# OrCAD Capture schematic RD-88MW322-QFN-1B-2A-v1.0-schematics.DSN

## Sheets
1 BLOCK DIAGRAM, TOC: title: RD-88MW322-QFN-1B-2A V1.0 Schematic; rev: 1
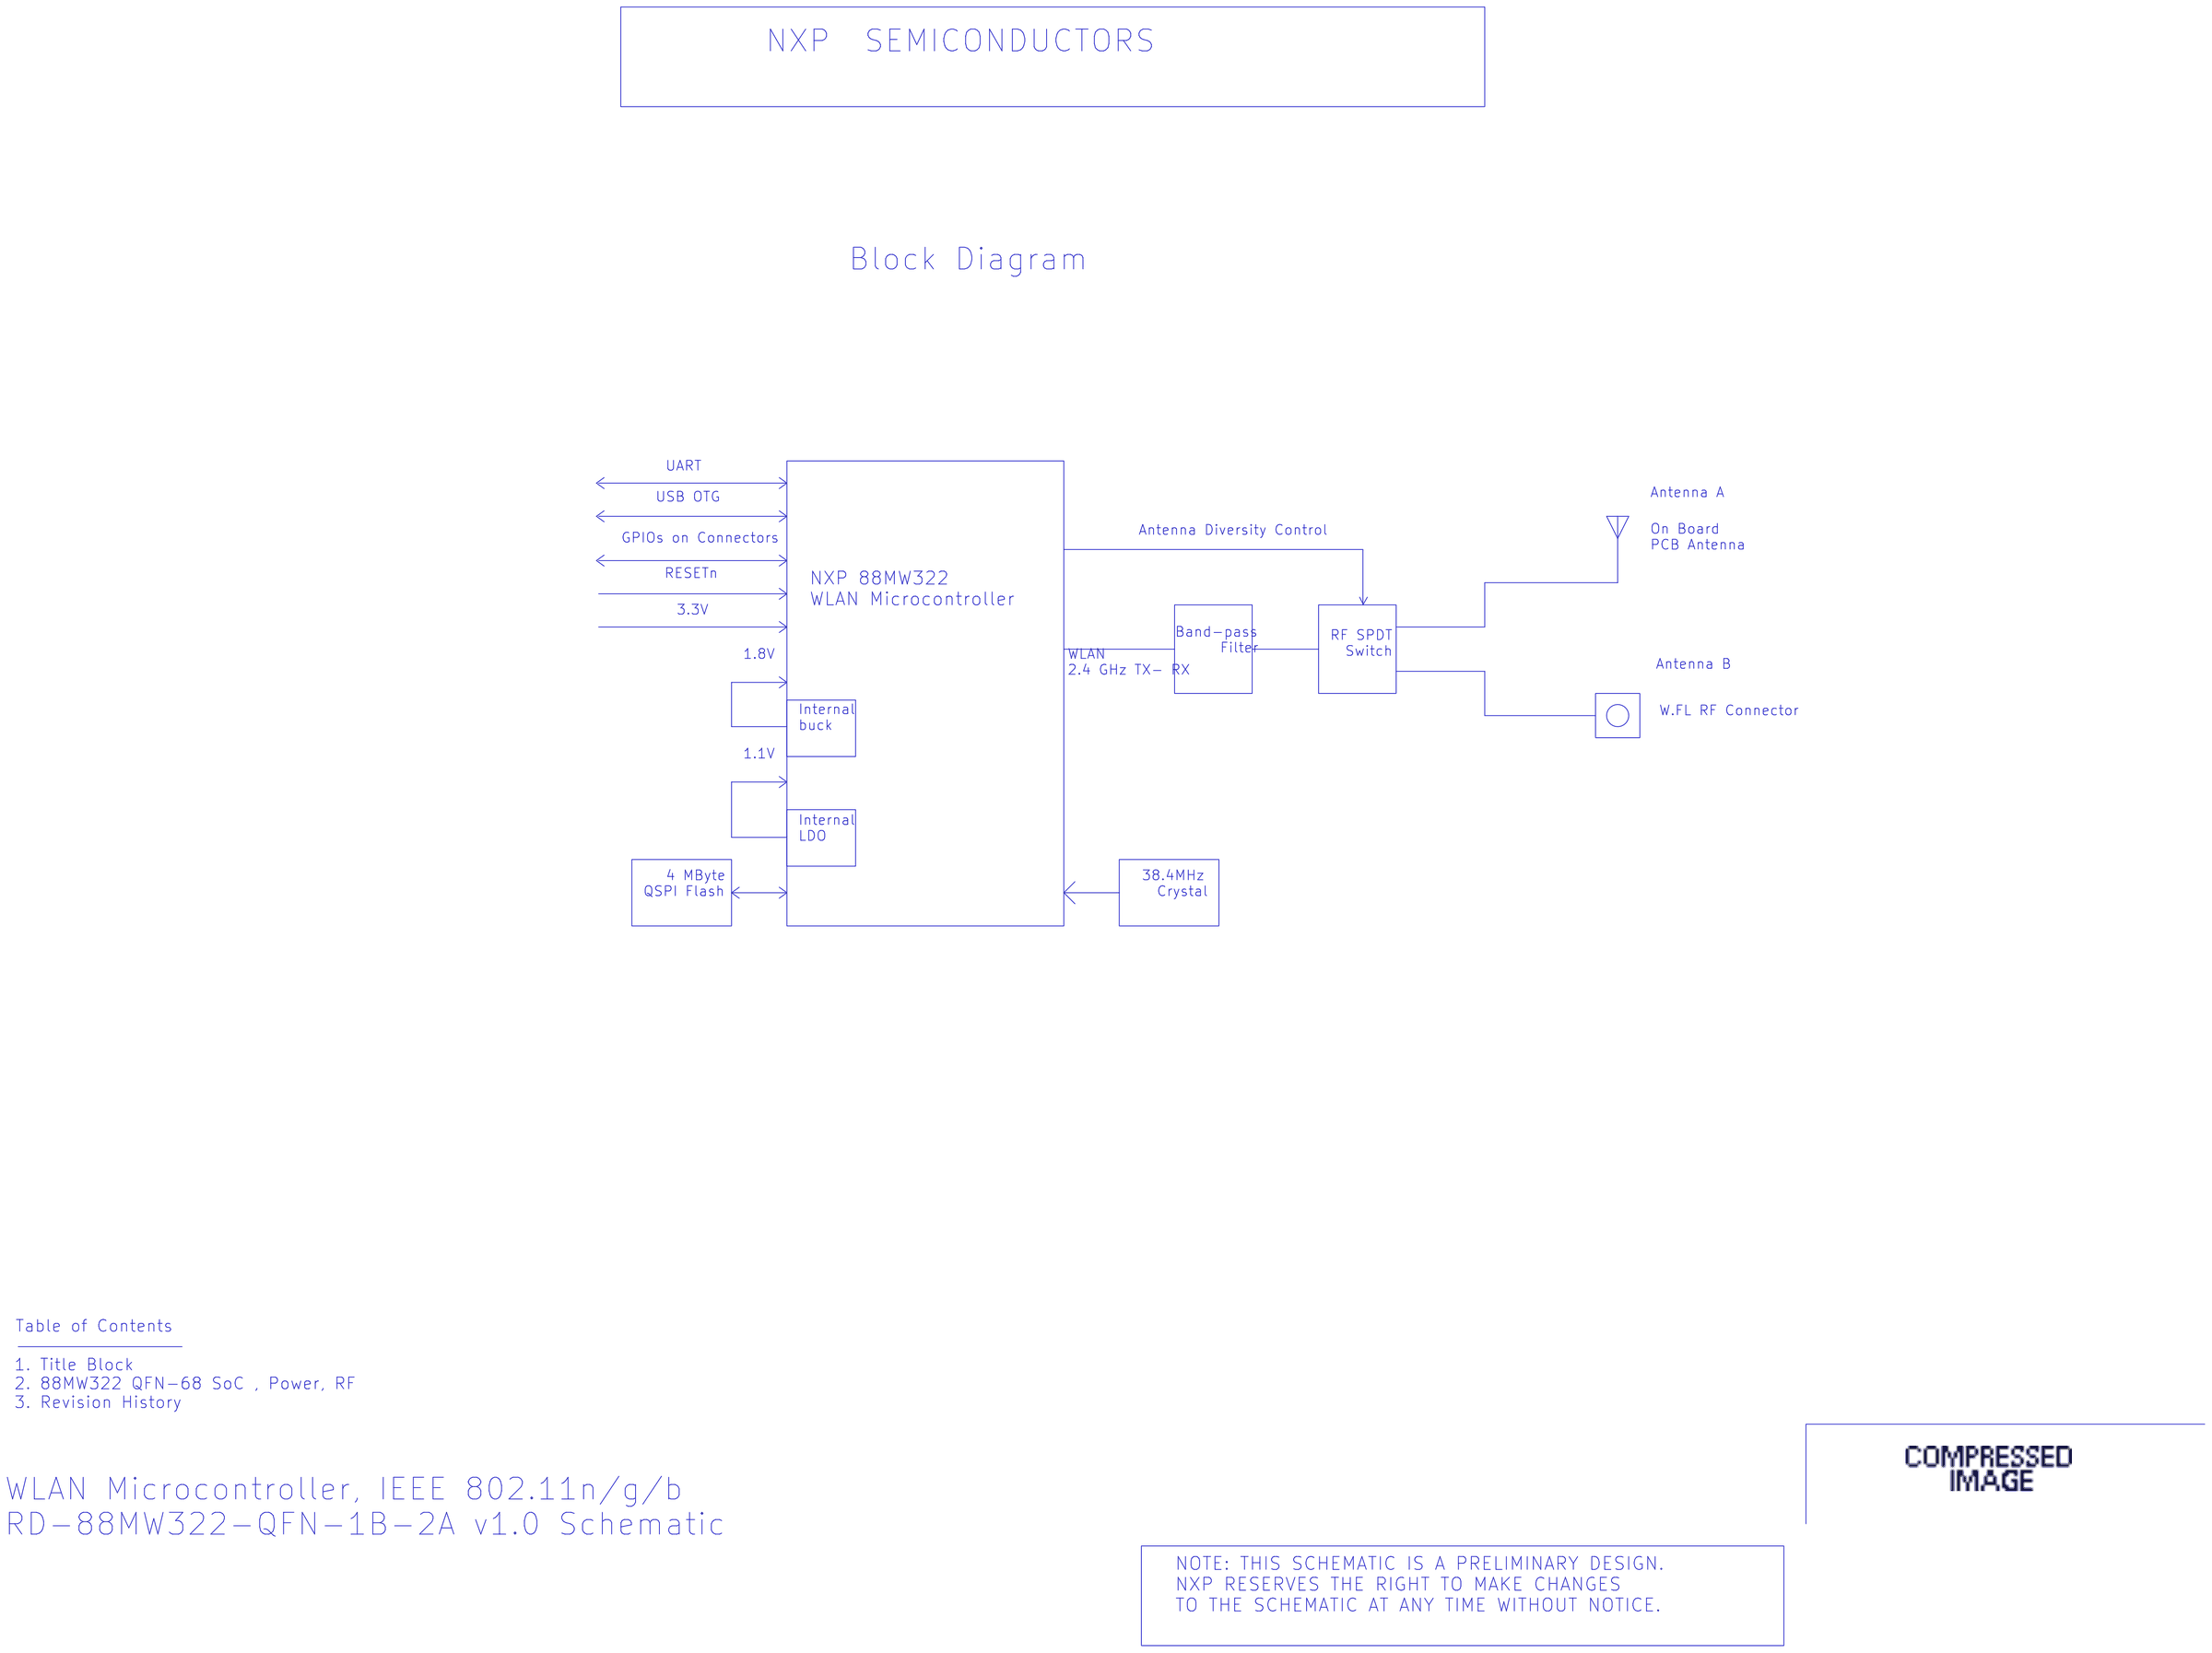
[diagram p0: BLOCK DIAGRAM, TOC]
2 88MW322 QFN-88 SoC_Power_RF: size C
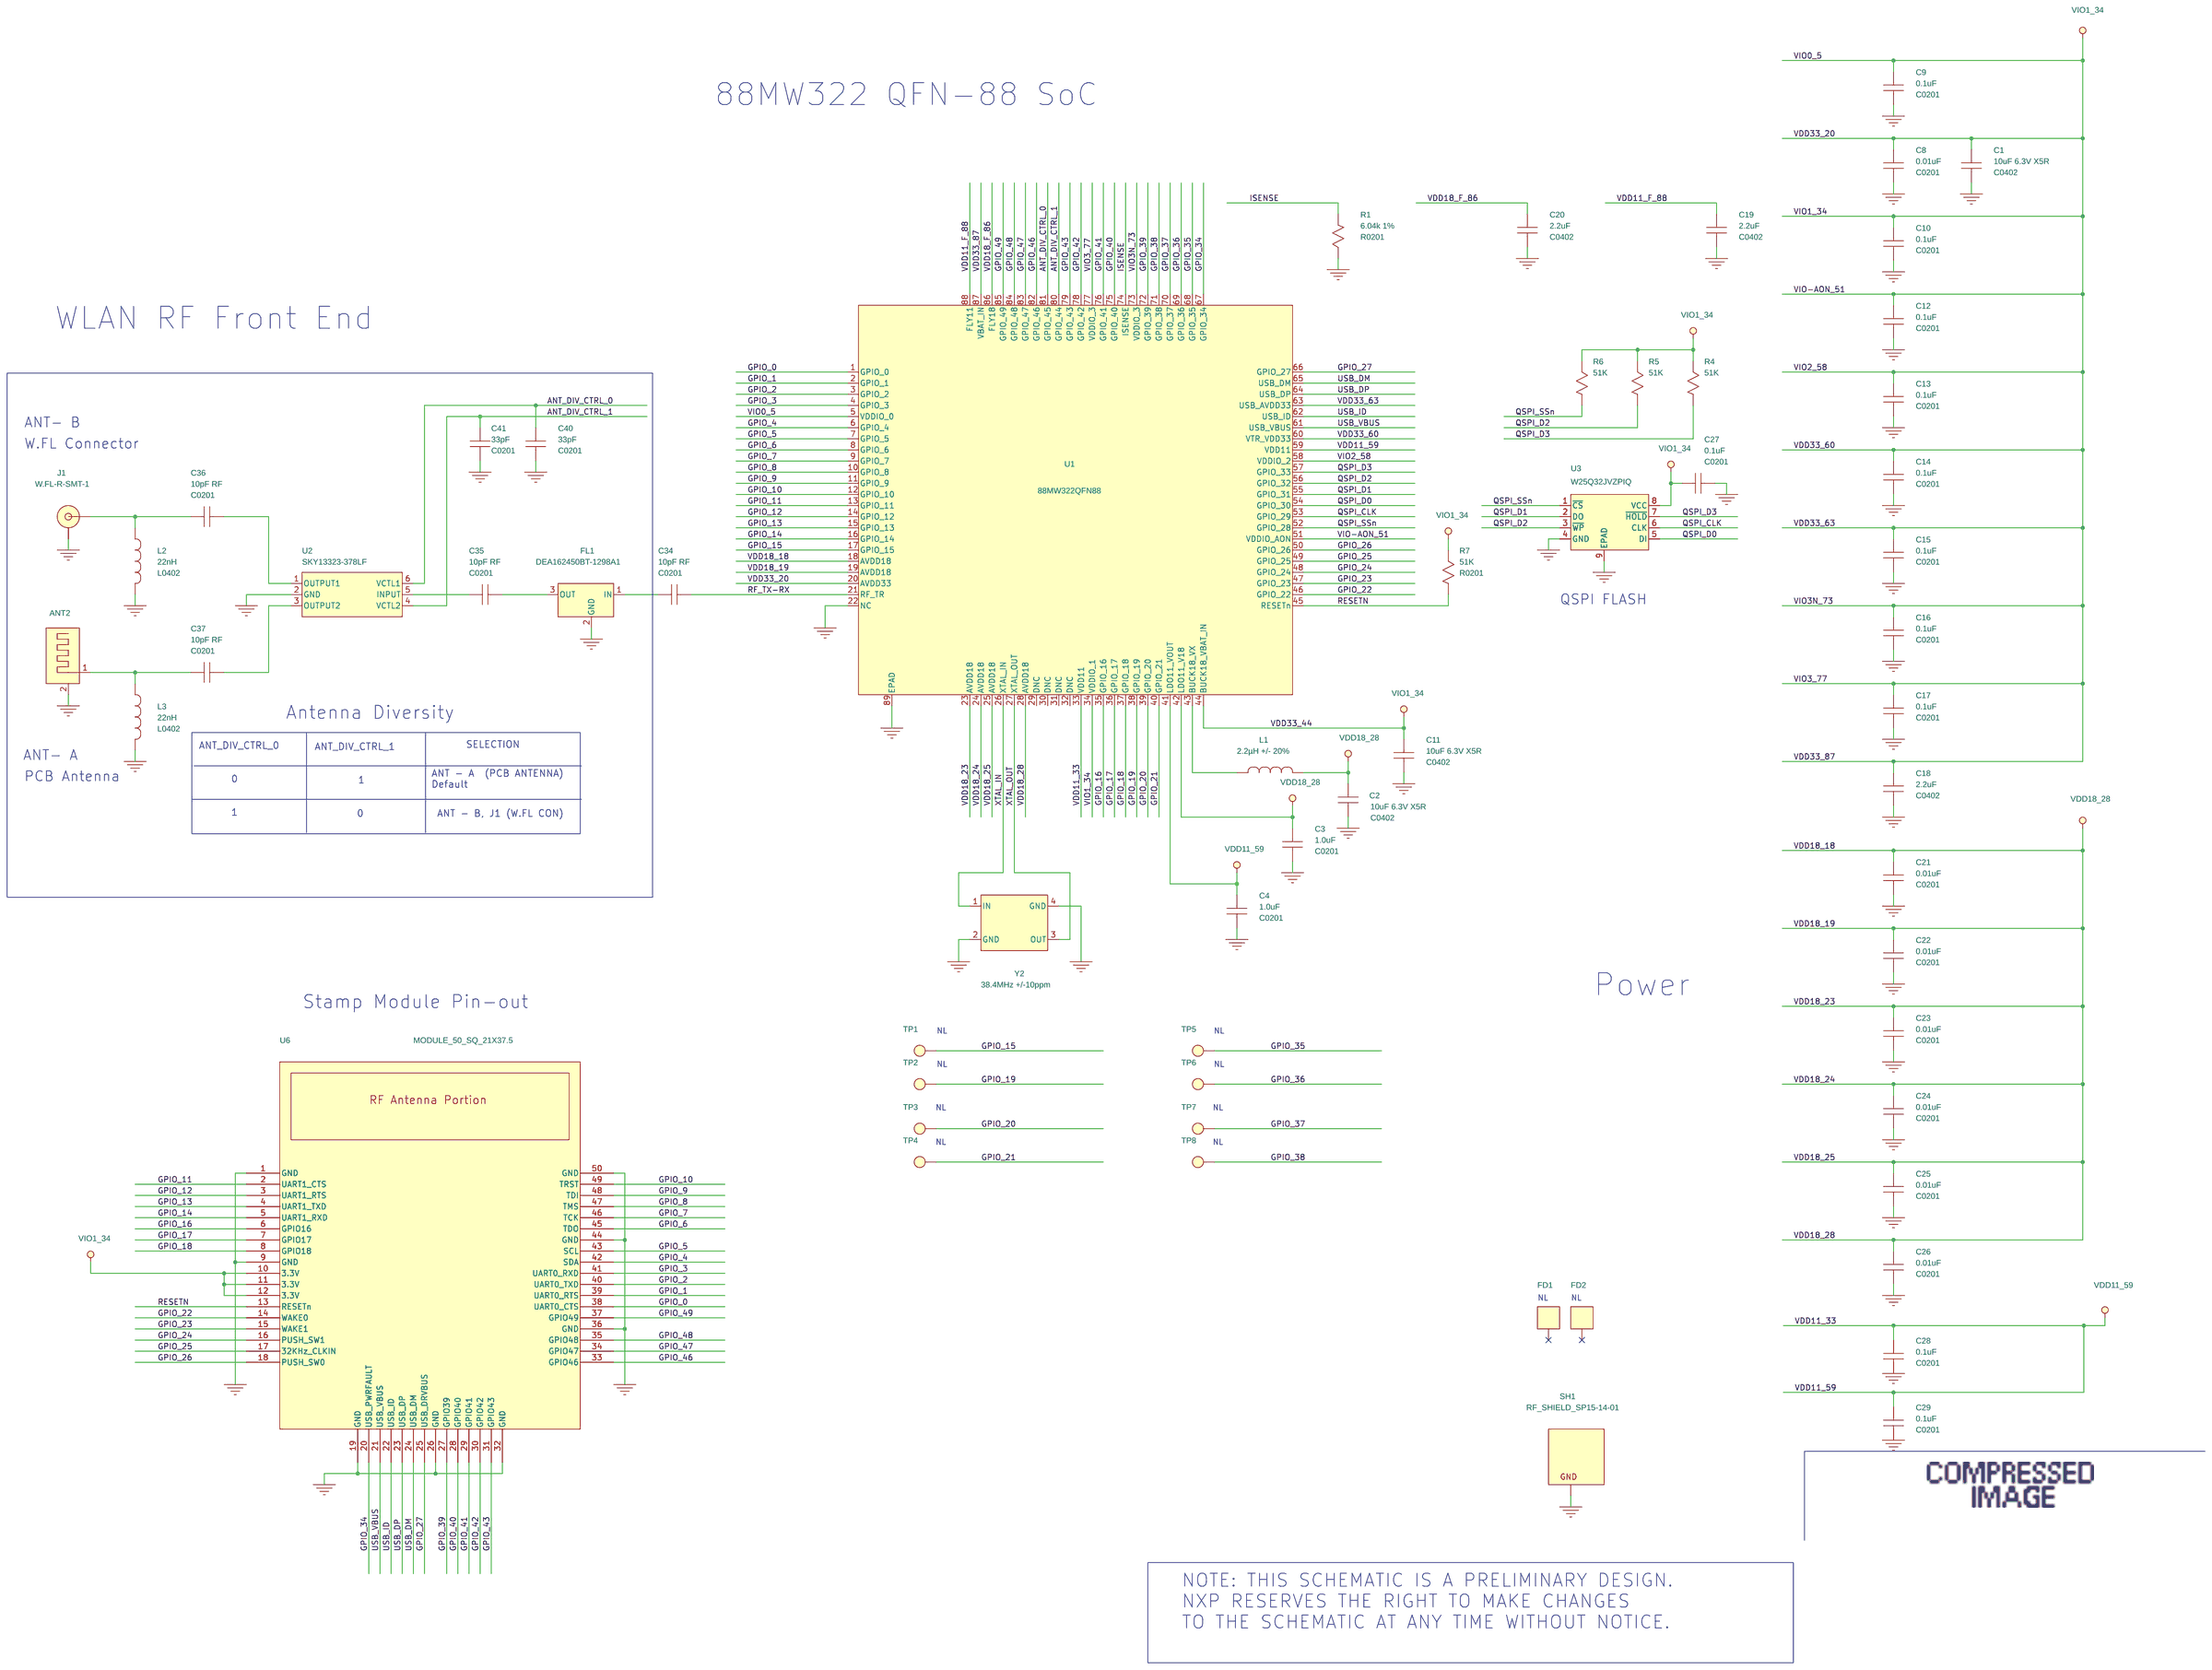
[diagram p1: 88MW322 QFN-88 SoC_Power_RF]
3 REVISION HISTORY
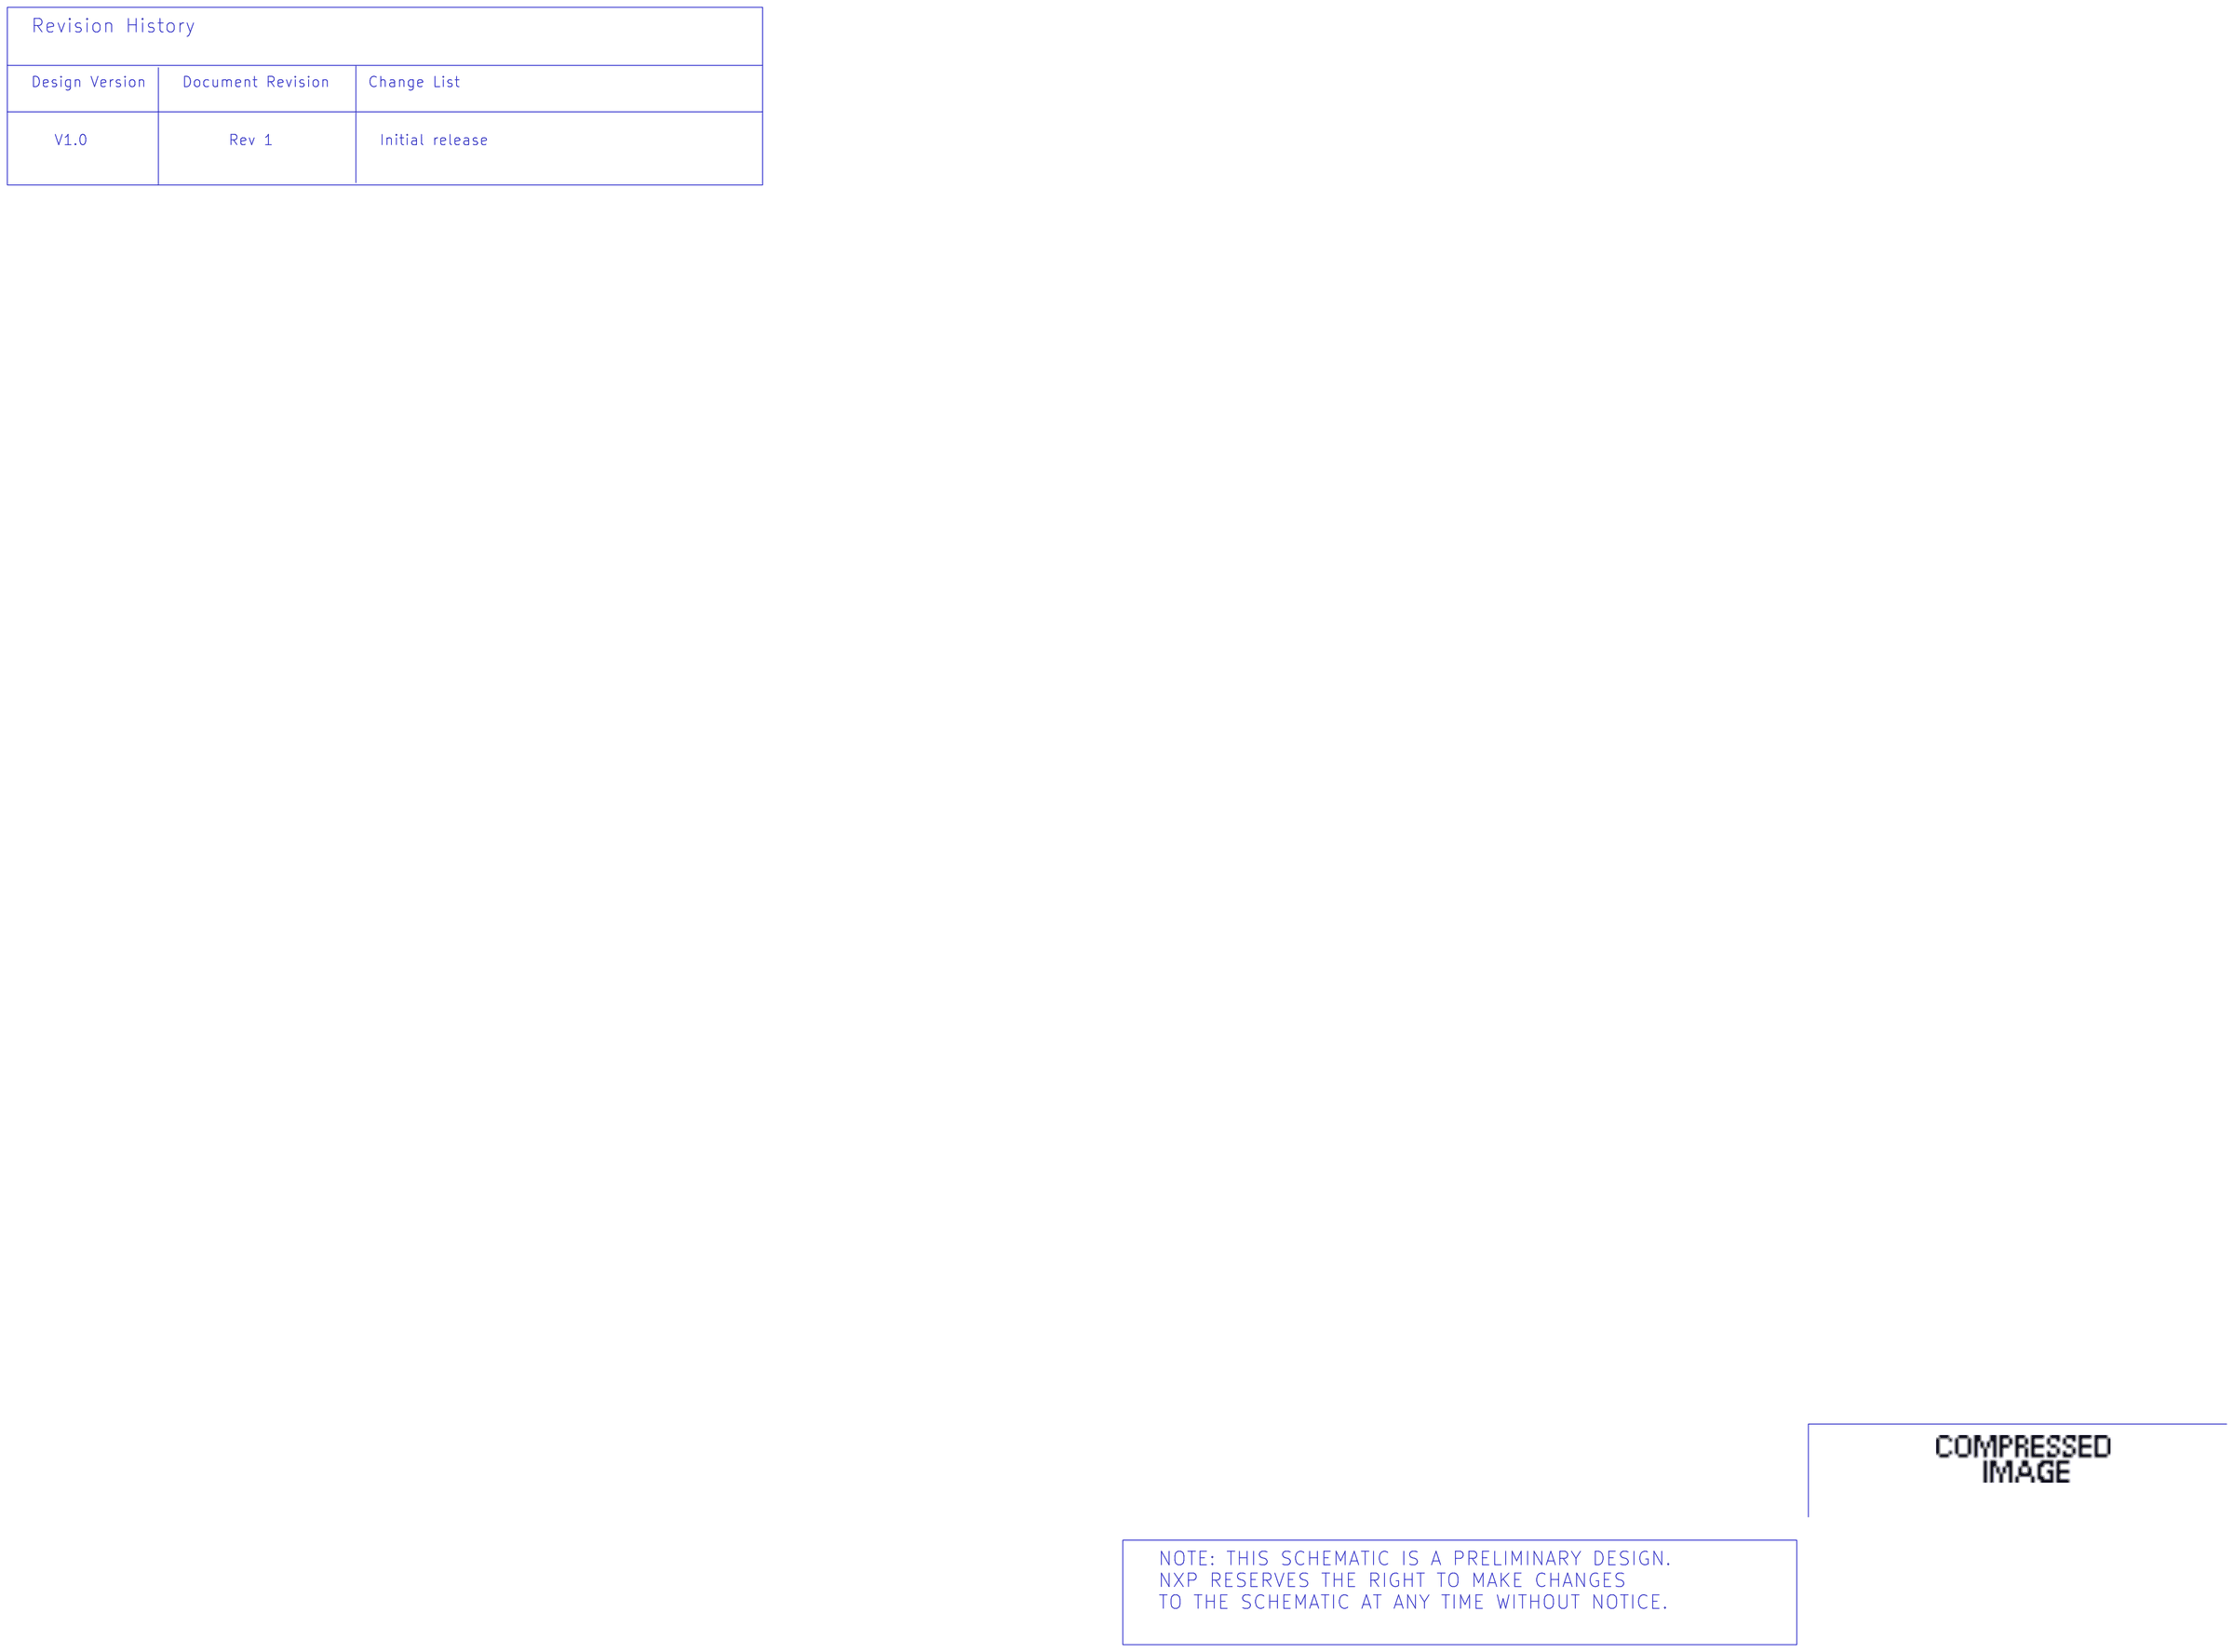
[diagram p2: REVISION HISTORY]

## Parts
ANT2  PCB Micro-strip Patch Antenna  [SDIO_ANT_SINGLE_INVERT_SOUTH]
C1  10uF 6.3V X5R  [C0402]
C2  10uF 6.3V X5R  [C0402]
C3  1.0uF  [C0201]
C4  1.0uF  [C0201]
C8  0.01uF  [C0201]
C9  0.1uF  [C0201]
C10  0.1uF  [C0201]
C11  10uF 6.3V X5R  [C0402]
C12  0.1uF  [C0201]
C13  0.1uF  [C0201]
C14  0.1uF  [C0201]
C15  0.1uF  [C0201]
C16  0.1uF  [C0201]
C17  0.1uF  [C0201]
C18  2.2uF  [C0402]
C19  2.2uF  [C0402]
C20  2.2uF  [C0402]
C21  0.01uF  [C0201]
C22  0.01uF  [C0201]
C23  0.01uF  [C0201]
C24  0.01uF  [C0201]
C25  0.01uF  [C0201]
C26  0.01uF  [C0201]
C27  0.1uF  [C0201]
C28  0.1uF  [C0201]
C29  0.1uF  [C0201]
C34  10pF RF  [C0201]
C35  10pF RF  [C0201]
C36  10pF RF  [C0201]
C37  10pF RF  [C0201]
C40  33pF  [C0201]
C41  33pF  [C0201]
FD1  NL  [FIDUCIAL_25MP-40MM]
FD2  NL  [FIDUCIAL_25MP-40MM]
FL1  DEA162450BT-1298A1  [RF_TDK_BPF_LGA3_1.6X0.8]
J1  W.FL-R-SMT-1  [CON_WFL_MALE_2X2MM_SMD4]
L1  2.2µH +/- 20%  [L0805]
L2  22nH  [L0402]
L3  22nH  [L0402]
R1  6.04k 1%  [R0201]
R4  51K  [R0201]
R5  51K  [R0201]
R6  51K  [R0201]
R7  51K  [R0201]
SH1  RF_SHIELD_SP15-14-01  [RF_SHIELD_SP15-14-01]
TP1  NL  [TP_SMPAD30MIL]
TP2  NL  [TP_SMPAD30MIL]
TP3  NL  [TP_SMPAD30MIL]
TP4  NL  [TP_SMPAD30MIL]
TP5  NL  [TP_SMPAD30MIL]
TP6  NL  [TP_SMPAD30MIL]
TP7  NL  [TP_SMPAD30MIL]
TP8  NL  [TP_SMPAD30MIL]
U1  88MW322QFN88  [MRVL_QFN88LP40_10X10_NXU]
U2  SKY13323-378LF  [RF_SKY_SPDT_MLPD6P35_1X1X0.5]
U3  W25Q32JVZPIQ  [IC_WBOND_WSON8_ZP]
U6  MODULE  [MODULE_50_SQ_21X37.5]
Y2  38.4MHz +/-10ppm  [XTAL_TXC_SMD_1.6X1.2MM]

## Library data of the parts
ANT2 = ON-Board_ANT_0
C1 C2 C11 = CAP_NP: CAP CER 10uF 20% 6.3V X5R 0402 (0.5MM); ManufacturerPn1: Murata GRM155R60J106ME44D; ManufacturerPn2: TDK C1005X5R0J106M050BC; Mfg1MrvlAvl: 0; Mfg2MrvlAvl: 0; Mfg3MrvlAvl: 0; ObsoletedByPartID: 0; Part Number: 5044-001-002287; Part Type: CAP; SourceLibrary: PARTS.OLB
C3 C4 = CAP_NP: CAP CER 1uF 20% 6.3V X5R 0201 (0.3MM); ManufacturerPn1: TDK C0603X5R0J105M030BC; Mfg1MrvlAvl: 0; Mfg2MrvlAvl: 0; Mfg3MrvlAvl: 0; ObsoletedByPartID: 0; Part Number: 5044-001-002324; Part Type: CAP; SourceLibrary: PARTS.OLB
C8 C21-C26 = CAP_NP: CAP CER 0.01uF 10% 10V X7R 0201 (0.3MM); ManufacturerPn1: MURATA GRM033R71A103K; ManufacturerPn2: WALSIN 0201B103K100CT; ManufacturerPn3: TDK C0603X7R1A103K; Mfg1MrvlAvl: 0; Mfg2MrvlAvl: 0; Mfg3MrvlAvl: 0; ObsoletedByPartID: 0; Part Number: 5044-001-001487; Part Type: CAP; SourceLibrary: PARTS.OLB
C9 C10 C12-C17 C27-C29 = CAP_NP: CAP CER 0.1uF 10% 6.3V X5R 0201 (0.3MM); ManufacturerPn1: MURATA GRM033R60J104K; ManufacturerPn2: WALSIN 0201X104K6R3CT; ManufacturerPn3: TDK C0603X5R0J104K; Mfg1MrvlAvl: 0; Mfg2MrvlAvl: 0; Mfg3MrvlAvl: 0; ObsoletedByPartID: 0; Part Number: 5044-001-001493; Part Type: CAP; SourceLibrary: PARTS.OLB
C18-C20 = CAP_NP: CAP CER 2.2UF 10% 6.3V  X5R 0402 (0.3MM); ManufacturerPn1: TDK C1005X5R0J225K050BC; Mfg1MrvlAvl: 0; Mfg2MrvlAvl: 0; Mfg3MrvlAvl: 0; ObsoletedByPartID: 0; Part Number: 5044-001-002325; Part Type: CAP; SourceLibrary: PARTS.OLB
C34-C37 = CAP_NP: CAP CER 10pF 5% 25V C0H 0201 (0.3MM); ManufacturerPn1: Murata GJM0336C1E100JB01; Mfg1MrvlAvl: 0; Mfg2MrvlAvl: 0; Mfg3MrvlAvl: 0; ObsoletedByPartID: 0; Part Number: 5044-001-002305; Part Type: CAP; SourceLibrary: PARTS.OLB
C40 C41 = CAP_NP: CAP CER 33pF 5% 25V C0G 0201 (0.3MM); ManufacturerPn1: MURATA GRM0335C1E330J; ManufacturerPn2: WALSIN 0201N330J250LT; ManufacturerPn3: TDK C0603C0G1E330J; Mfg1MrvlAvl: 0; Mfg2MrvlAvl: 0; Mfg3MrvlAvl: 0; Notes: 50V ok if 25V not available; ObsoletedByPartID: 0; Part Number: 5044-001-001469; Part Type: CAP; SourceLibrary: PARTS.OLB
FD1 FD2 = FIDUCIAL: FIDUCIAL ULTRA SMALL 25 MIL PAD / 40 MIL SOLDER MASK OPENING; ManufacturerPn1: FIDUCIAL_25MPAD-40MMASK; ManufacturerPn2: NA; ManufacturerPn3: NA; Mfg1MrvlAvl: 0; Mfg2MrvlAvl: 0; Mfg3MrvlAvl: 0; ObsoletedByPartID: 0; Part Number: FIDUCIAL_25MPAD-40MMASK; Part Type: MECH; SourceLibrary: PARTS.OLB
FL1 = RF_DEA162450BT-1298A1: FILTER BP 2450MHz +/-50MHz IL=1.3dB MAX LGA-3 1.6x0.8x0.6mm; ManufacturerPn1: TDK DEA162450BT-1298A1; Mfg1MrvlAvl: 0; Mfg2MrvlAvl: 0; Mfg3MrvlAvl: 0; ObsoletedByPartID: 0; Part Number: 5044-001-002438; Part Type: FILTER; SourceLibrary: PARTS.OLB
J1 = CON_W.FL-R-SMT-1: CONN RF W.FL COAX MALE 2.0x2.0x0.85MM  SMD; ManufacturerPn1: HIROSE W.FL-R-SMT-1(10); ManufacturerPn2: IPEX 20369-001E; Mfg1MrvlAvl: 0; Mfg2MrvlAvl: 0; Mfg3MrvlAvl: 0; ObsoletedByPartID: 0; Part Number: 5044-001-002271; Part Type: CONN; SourceLibrary: PARTS.OLB
L1 = INDUCTOR: IND WWC 2.2UH +/-20% 1000mA 0805 SMD; ManufacturerPn1: TAIYO YUDEN BRC2012T2R2MD; Mfg1MrvlAvl: 0; Mfg2MrvlAvl: 0; Mfg3MrvlAvl: 0; ObsoletedByPartID: 0; Part Number: 5044-001-002447; Part Type: IND; SourceLibrary: PARTS.OLB
L2 L3 = INDUCTOR: IND MLC 22nH +/-5% 300mA 0402 SMD Hi-Q; ManufacturerPn1: MURATA LQG15HS22NJ02; ManufacturerPn2: TDK MLG1005S22NJ; Mfg1MrvlAvl: 0; Mfg2MrvlAvl: 0; Mfg3MrvlAvl: 0; ObsoletedByPartID: 0; Part Number: 5044-001-001658; Part Type: IND; SourceLibrary: PARTS.OLB
R1 = RES: RES THICK FILM 6.04K OHM 1/20W 1% 0201 SMD; ManufacturerPn1: Cyntec PFR03S-6041-FNH; ManufacturerPn2: Walsin WR02X6041FAL; ManufacturerPn3: Yageo RC0201FR-076K04L; Mfg1MrvlAvl: 0; Mfg2MrvlAvl: 0; Mfg3MrvlAvl: 0; ObsoletedByPartID: 0; Part Number: 5044-001-000263; ProtoPriceTargetPerUnit: 0.00800; SourceLibrary: PARTS.OLB
R4-R7 = RES: RES THICK FILM 51K OHM 1/20W 5% 0201 SMD; ManufacturerPn1: Cyntec PFR03S-513-JNH; ManufacturerPn2: Walsin WR02X513 JAL; ManufacturerPn3: Yageo RC0201JR-0751KL; Mfg1MrvlAvl: 0; Mfg2MrvlAvl: 0; Mfg3MrvlAvl: 0; ObsoletedByPartID: 0; Part Number: 5044-001-000577; ProtoPriceTargetPerUnit: 0.00500; SourceLibrary: PARTS.OLB
SH1 = RF_SHIELD_TH2: RF SHIELD RD-MC200W8801-V2 1-PC SPTE 0.15MM +/-0.01MM THICK 28x18.4x2mm; ManufacturerPn1: BRIGHT-LINK SP15-14-01; ManufacturerPn2: AKS ASH0194; Mfg1MrvlAvl: 0; Mfg2MrvlAvl: 0; Mfg3MrvlAvl: 0; ObsoletedByPartID: 0; Part Number: 5044-001-002392; Part Type: MECH; SourceLibrary: PARTS.OLB
TP1-TP8 = TESTPOINT: MRVL SMD TESTPOINT SIZE 30 MIL; ManufacturerPn1: MRVL TP30MIL; Mfg1MrvlAvl: 0; Mfg2MrvlAvl: 0; Mfg3MrvlAvl: 0; ObsoletedByPartID: 0; Part Number: TP30MIL; Part Type: PCB; SourceLibrary: PARTS.OLB
U1 = 88MW322_QFN88L: IC MRVL 88MW322 WLAN MICROCONTROLLER SoC QFN88L 0.4mm 10x10x0.9mm; ManufacturerPn1: MRVL 88MW322-A0-NXU2E000; Mfg1MrvlAvl: 0; Mfg2MrvlAvl: 0; Mfg3MrvlAvl: 0; Notes: Pin compatible with 88MW302 (QFN88); ObsoletedByPartID: 0; Part Number: 88MW322A0NXU2E000; Part Type: Marvell; SourceLibrary: PARTS.OLB
U2 = RF_SKY_SPDT_SKY13323-378LF: IC RF SW SPDT 0.1GHz-3GHz VCTL 1.8V-5V MLPD-6 0.35mm 1x1x0.5mm; ManufacturerPn1: SKY SKY13323-378LF; Mfg1MrvlAvl: 0; Mfg2MrvlAvl: 0; Mfg3MrvlAvl: 0; ObsoletedByPartID: 0; OneHundredKPerMoPriceTarget: 0.00000; OneKkPerMoPriceTarget: 0.00000; Part Number: 5044-001-002253; Part Type: IC; ProtoPriceTargetPerUnit: 0.00000; SourceLibrary: PARTS.OLB
U3 = IC_WBOND_SQPI_FLASH_DQIO_WSON8: IC SPI+QPI SRL FLASH DUAL/QUAD I/O 32M 2.7-3.6V 133MHZ WSON-8 6x5x0.8mm; ManufacturerPn1: MACRONIX MX25L3233FZNI-08G; ManufacturerPn2: WINBOND W25Q32JVZPIQ; Mfg1MrvlAvl: 0; Mfg2MrvlAvl: 0; Mfg3MrvlAvl: 0; Notes: Drop-in replacement for W25Q32FVZPIG (EOL); ObsoletedByPartID: 0; Part Number: 5044-001-002937; Part Type: IC; SourceLibrary: PARTS.OLB
U6 = MODULE_4
Y2 = XTAL_TXC_SMD_1.6X1.2MM: XTAL 38.4MHz +/-10ppm FUND 10pF 60OHM -30C/+85C SMD 1.6X1.2X0.4mm; ManufacturerPn1: TXC 8Q38470003; Mfg1MrvlAvl: 0; Mfg2MrvlAvl: 0; Mfg3MrvlAvl: 0; ObsoletedByPartID: 0; Part Number: 5044-001-002327; Part Type: XTAL/OSC; SourceLibrary: PARTS.OLB

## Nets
+1.1V: C4.1 C28.1 C29.1 U1.33(VDD11) U1.41(LDO11_VOUT) U1.59(VDD11)
+1.8V: C2.1 C3.1 C21.1 C22.1 C23.1 C24.1 C25.1 C26.1 L1.2 U1.18(AVDD18) U1.19(AVDD18) U1.23(AVDD18) U1.24(AVDD18) U1.25(AVDD18) U1.28(AVDD18) U1.42(LDO11_V18)
+3.3V: C1.1 C8.1 C9.1 C10.1 C11.1 C12.1 C13.1 C14.1 C15.1 C16.1 C17.1 C18.1 C27.1 R4.1 R5.1 R6.1 R7.1 U1.5(VDDIO_0) U1.20(AVDD33) U1.34(VDDIO_1) U1.44(BUCK18_VBAT_IN) U1.51(VDDIO_AON) U1.58(VDDIO_2) U1.60(VTR_VDD33) U1.63(USB_AVDD33) U1.73(VDDIO_3) U1.77(VDDIO_3) U1.87(VBAT_IN) U3.8(VCC) U6.10(3.3V) U6.11(3.3V) U6.12(3.3V)
GND_POWER: ANT2.2 C1.2 C2.2 C3.2 C4.2 C8.2 C9.2 C10.2 C11.2 C12.2 C13.2 C14.2 C15.2 C16.2 C17.2 C18.2 C19.2 C20.2 C21.2 C22.2 C23.2 C24.2 C25.2 C26.2 C27.2 C28.2 C29.2 C40.2 C41.2 FL1.2(GND) J1.2(GND) J1.3(GND) J1.4(GND) L2.2 L3.2 R1.1 SH1.1(GND) SH1.2(GND) U1.22(NC) U1.89(EPAD) U2.2(GND) U3.4(GND) U3.9(EPAD) U6.1(GND) U6.9(GND) U6.19(GND) U6.26(GND) U6.32(GND) U6.36(GND) U6.44(GND) U6.50(GND) Y2.2(GND) Y2.4(GND)
VDD11_F_88: C19.1 U1.88(FLY11)
VDD18_F_86: C20.1 U1.86(FLY18)
ANT_DIV_CTRL_0: C40.1 U1.81(GPIO_45) U2.6(VCTL1)
ANT_DIV_CTRL_1: C41.1 U1.80(GPIO_44) U2.4(VCTL2)
GPIO_0: U1.1(GPIO_0) U6.38(UART0_CTS)
GPIO_1: U1.2(GPIO_1) U6.39(UART0_RTS)
GPIO_2: U1.3(GPIO_2) U6.40(UART0_TXD)
GPIO_3: U1.4(GPIO_3) U6.41(UART0_RXD)
GPIO_4: U1.6(GPIO_4) U6.42(SDA)
GPIO_5: U1.7(GPIO_5) U6.43(SCL)
GPIO_6: U1.8(GPIO_6) U6.45(TDO)
GPIO_7: U1.9(GPIO_7) U6.46(TCK)
GPIO_8: U1.10(GPIO_8) U6.47(TMS)
GPIO_9: U1.11(GPIO_9) U6.48(TDI)
GPIO_10: U1.12(GPIO_10) U6.49(TRST)
GPIO_11: U1.13(GPIO_11) U6.2(UART1_CTS)
GPIO_12: U1.14(GPIO_12) U6.3(UART1_RTS)
GPIO_13: U1.15(GPIO_13) U6.4(UART1_TXD)
GPIO_14: U1.16(GPIO_14) U6.5(UART1_RXD)
GPIO_15: TP1.1 U1.17(GPIO_15)
GPIO_16: U1.35(GPIO_16) U6.6(GPIO16)
GPIO_17: U1.36(GPIO_17) U6.7(GPIO17)
GPIO_18: U1.37(GPIO_18) U6.8(GPIO18)
GPIO_19: TP2.1 U1.38(GPIO_19)
GPIO_20: TP3.1 U1.39(GPIO_20)
GPIO_21: TP4.1 U1.40(GPIO_21)
GPIO_22: U1.46(GPIO_22) U6.14(WAKE0)
GPIO_23: U1.47(GPIO_23) U6.15(WAKE1)
GPIO_24: U1.48(GPIO_24) U6.16(PUSH_SW1)
GPIO_25: U1.49(GPIO_25) U6.17(32KHz_CLKIN)
GPIO_26: U1.50(GPIO_26) U6.18(PUSH_SW0)
GPIO_27: U1.66(GPIO_27) U6.25(USB_DRVBUS)
GPIO_34: U1.67(GPIO_34) U6.20(USB_PWRFAULT)
GPIO_35: TP5.1 U1.68(GPIO_35)
GPIO_36: TP6.1 U1.69(GPIO_36)
GPIO_37: TP7.1 U1.70(GPIO_37)
GPIO_38: TP8.1 U1.71(GPIO_38)
GPIO_39: U1.72(GPIO_39) U6.27(GPIO39)
GPIO_40: U1.75(GPIO_40) U6.28(GPIO40)
GPIO_41: U1.76(GPIO_41) U6.29(GPIO41)
GPIO_42: U1.78(GPIO_42) U6.30(GPIO42)
GPIO_43: U1.79(GPIO_43) U6.31(GPIO43)
GPIO_46: U1.82(GPIO_46) U6.33(GPIO46)
GPIO_47: U1.83(GPIO_47) U6.34(GPIO47)
GPIO_48: U1.84(GPIO_48) U6.35(GPIO48)
GPIO_49: U1.85(GPIO_49) U6.37(GPIO49)
ISENSE: R1.2 U1.74(ISENSE)
QSPI_CLK: U1.53(GPIO_29) U3.6(CLK)
QSPI_D0: U1.54(GPIO_30) U3.5(DI)
QSPI_D1: U1.55(GPIO_31) U3.2(DO)
QSPI_D2: R5.2 U1.56(GPIO_32) U3.3(~{WP})
QSPI_D3: R4.2 U1.57(GPIO_33) U3.7(~{HOLD})
QSPI_SSn: R6.2 U1.52(GPIO_28) U3.1(~{CS})
RESETN: R7.2 U1.45(RESETn) U6.13(RESETn)
RF_TX-RX: C34.2 U1.21(RF_TR)
USB_DM: U1.65(USB_DM) U6.24(USB_DM)
USB_DP: U1.64(USB_DP) U6.23(USB_DP)
USB_ID: U1.62(USB_ID) U6.22(USB_ID)
USB_VBUS: U1.61(USB_VBUS) U6.21(USB_VBUS)
XTAL_IN: U1.26(XTAL_IN) Y2.1(IN)
XTAL_OUT: U1.27(XTAL_OUT) Y2.3(OUT)
N04866: L1.1 U1.43(BUCK18_VX)
N14504: C34.1 FL1.1(IN)
N14557: C35.2 FL1.3(OUT)
N14751: C35.1 U2.5(INPUT)
N14808: C36.2 U2.1(OUTPUT1)
N14819: C37.2 U2.3(OUTPUT2)
N15831: C36.1 J1.1(SIG) L2.1
N15838: ANT2.1 C37.1 L3.1

Not connected (* = marked no-connect by the designer): FD1 1*; FD2 1*; U1 29(DNC) 30(DNC) 31(DNC) 32(DNC)

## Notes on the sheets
sheet 1
- NXP  SEMICONDUCTORS
- Block Diagram
- UART
- USB OTG
- Antenna A
- GPIOs on Connectors
- Antenna Diversity Control
- On Board
  PCB Antenna
- RESETn
- NXP 88MW322
  WLAN Microcontroller
- 3.3V
- Band-pass
        Filter
- RF SPDT
    Switch
- 1.8V
- WLAN
  2.4 GHz TX- RX
- Antenna B
- Internal
  buck
- W.FL RF Connector
- 1.1V
- Internal
  LDO
- 4 MByte
  QSPI Flash
- 38.4MHz
    Crystal
- Table of Contents
- 1. Title Block
  2. 88MW322 QFN-68 SoC , Power, RF
  3. Revision History
- WLAN Microcontroller, IEEE 802.11n/g/b
  RD-88MW322-QFN-1B-2A v1.0 Schematic
- NOTE: THIS SCHEMATIC IS A PRELIMINARY DESIGN.
  NXP RESERVES THE RIGHT TO MAKE CHANGES
  TO THE SCHEMATIC AT ANY TIME WITHOUT NOTICE.
sheet 2
- 88MW322 QFN-88 SoC
- WLAN RF Front End
- ANT- B
- W.FL Connector
- QSPI FLASH
- Antenna Diversity
- ANT_DIV_CTRL_0
- ANT_DIV_CTRL_1
- SELECTION
- ANT- A
- PCB Antenna
- ANT - A  (PCB ANTENNA)
  Default
- 0
- 1
- 1
- 0
- ANT - B, J1 (W.FL CON)
- Power
- Stamp Module Pin-out
- NL
- NL
- NL
- NL
- NL
- NL
- NL
- NL
- NL
- NL
- NOTE: THIS SCHEMATIC IS A PRELIMINARY DESIGN.
  NXP RESERVES THE RIGHT TO MAKE CHANGES
  TO THE SCHEMATIC AT ANY TIME WITHOUT NOTICE.
sheet 3
- Revision History
- Design Version
- Document Revision
- Change List
- V1.0
- Rev 1
- Initial release
- NOTE: THIS SCHEMATIC IS A PRELIMINARY DESIGN.
  NXP RESERVES THE RIGHT TO MAKE CHANGES
  TO THE SCHEMATIC AT ANY TIME WITHOUT NOTICE.
